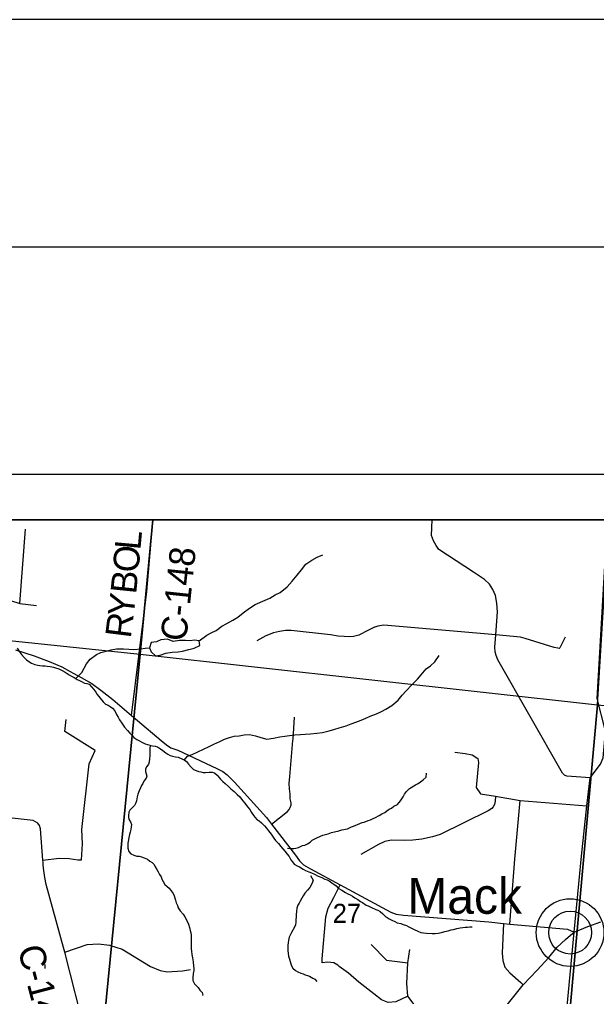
# Model space of a CAD drawing. Extents: x 0 to 34, y 0 to 22.
# Drawn here: x 4.78 to 6.05, y 19.852 to 22 of the extents above; entities that cross this region are included whole.
import ezdxf

# ---------------------------------------------------------------- set-up
doc = ezdxf.new("R2010")
doc.units = 0
for name, color, linetype in [('GM_X_Corporation', 7, 'Continuous'), ('GM_X_County_Road', 7, 'Continuous'), ('GM_X_County_Road_Text', 7, 'Continuous'), ('GM_X_Minor_Lake', 7, 'Continuous'), ('GM_X_Minor_River', 7, 'Continuous'), ('GM_X_Section_Text', 7, 'Continuous'), ('GM_X_State_Route', 7, 'Continuous'), ('GM_X_Township_Road', 7, 'Continuous'), ('GM_X_Unincorporated', 7, 'Continuous'), ('GM_X_Unincorporated_Location', 7, 'Continuous'), ('GM_X_Unincorporated_Text', 7, 'Continuous'), ('SH_Border', 7, 'Continuous'), ('SH_Cut_Line', 7, 'Continuous'), ('SH_Data', 7, 'Continuous')]:
    doc.layers.add(name, color=color, linetype=linetype)

msp = doc.modelspace()

# ---------------------------------------------------------------- linework, layer by layer
at = {"layer": 'GM_X_Corporation'}
for points in [[(8.9, 14.3814), (8.9, 20.9), (2.1, 20.9)], [(8.9, 17.1766), (8.9, 20.9), (4.0645, 20.9), (4.0111, 20.3696), (4.0006, 20.2658), (3.9936, 20.1954), (3.918, 19.4442), (3.8667, 18.9339), (3.8234, 18.553), (3.8126, 18.3974), (3.8023, 18.3182), (3.7454, 17.7286)]]:
    msp.add_lwpolyline(points, dxfattribs=at)
for points in [[(5.0731, 20.9), (4.0674, 20.9), (4.0476, 20.7082), (5.0456, 20.6041)], [(6.077, 20.9), (5.0731, 20.9), (5.0456, 20.6041), (6.0521, 20.4929)], [(4.0476, 20.7082), (5.0456, 20.6041), (4.9462, 19.5973), (3.9403, 19.7031)], [(6.0521, 20.4929), (5.9616, 19.4927), (4.9462, 19.5973), (5.0456, 20.6041)], [(7.0465, 20.3953), (6.9413, 19.3834), (5.9616, 19.4927), (6.0521, 20.4929)]]:
    msp.add_lwpolyline(points, close=True, dxfattribs=at)
at = {"layer": 'GM_X_County_Road'}
for points in [[(5.0263, 20.4698), (5.0598, 20.7421), (5.0709, 20.8695), (5.0742, 20.9)], [(6.0357, 20.3327), (5.9847, 20.3361), (5.9794, 20.3382), (5.975, 20.3429), (5.8326, 20.5921), (5.8291, 20.6013), (5.8268, 20.6093), (5.8263, 20.6196), (5.8283, 20.6466), (5.8319, 20.6973), (5.8303, 20.7167), (5.8274, 20.7335), (5.8218, 20.747), (5.8142, 20.7586), (5.8035, 20.7684), (5.779, 20.7844), (5.7029, 20.8343), (5.6968, 20.8433), (5.6908, 20.8538), (5.6869, 20.8656), (5.6878, 20.9)], [(6.0357, 20.3327), (6.0589, 20.3625), (6.0642, 20.3768), (6.0699, 20.4348), (6.0514, 20.507), (6.0739, 20.9)], [(4.7713, 20.6137), (4.8119, 20.6005), (4.8454, 20.5882), (4.8732, 20.5765), (4.8915, 20.5665), (4.9154, 20.5533), (4.939, 20.5402), (4.9587, 20.5256), (4.9851, 20.5048), (5.0263, 20.4698)], [(5.0263, 20.4698), (5.0396, 20.4585), (5.092, 20.4146), (5.1031, 20.4048), (5.1132, 20.3988), (5.1282, 20.3935), (5.2144, 20.3532), (5.2275, 20.3464), (5.2368, 20.3393), (5.2531, 20.323), (5.3235, 20.2455), (5.3348, 20.2308), (5.3873, 20.1625), (5.3964, 20.1497), (5.4053, 20.1411), (5.4206, 20.1324), (5.4859, 20.0972)], [(6.0003, 19.9928), (6.0164, 20.1604), (6.0288, 20.2712), (6.0357, 20.3327)], [(4.8321, 20.1419), (4.8317, 20.1469), (4.8314, 20.1513), (4.8263, 20.2202), (4.8238, 20.2275), (4.8202, 20.2325), (4.8097, 20.2385), (4.6962, 20.251)], [(4.9258, 19.7674), (4.8794, 19.9495), (4.8769, 19.9594), (4.8389, 20.0979), (4.8359, 20.1136), (4.8327, 20.1338), (4.8321, 20.1419)], [(5.4859, 20.0972), (5.5972, 20.0373), (5.6092, 20.0324), (5.6251, 20.0305), (5.813, 20.0156), (5.8451, 20.0124)], [(5.8451, 20.0124), (5.8423, 19.9472), (5.8438, 19.9306), (5.8477, 19.916), (5.8588, 19.9036), (5.8836, 19.8823), (5.8884, 19.8772)], [(5.8451, 20.0124), (5.859, 20.011), (5.9861, 19.9994), (6.0003, 19.9928)], [(5.9168, 18.9788), (5.9313, 19.1438), (5.9319, 19.1508), (5.942, 19.291), (5.9466, 19.3546), (5.9513, 19.4191), (5.9555, 19.4438), (5.9566, 19.4892), (5.9673, 19.6321), (5.979, 19.7684), (6.0003, 19.9928)]]:
    msp.add_lwpolyline(points, dxfattribs=at)
at = {"layer": 'GM_X_Minor_Lake'}
for points in [[(5.1179, 20.6324), (5.1055, 20.6373), (5.091, 20.6358), (5.0811, 20.6319), (5.07, 20.6299), (5.0663, 20.6185)], [(5.0663, 20.6186), (5.0694, 20.6094), (5.0795, 20.6011), (5.0894, 20.602), (5.1021, 20.607), (5.1158, 20.6085), (5.1291, 20.6093), (5.1386, 20.611), (5.1528, 20.6144), (5.1643, 20.6175), (5.177, 20.6233), (5.175, 20.634), (5.1651, 20.6354), (5.1552, 20.6337), (5.1453, 20.6344), (5.1317, 20.6343), (5.1179, 20.6324)]]:
    msp.add_lwpolyline(points, dxfattribs=at)
at = {"layer": 'GM_X_Minor_River'}
for points in [[(5.175, 20.634), (5.1919, 20.6465), (5.2015, 20.6512), (5.2127, 20.6566), (5.2255, 20.6657), (5.2359, 20.6719), (5.2494, 20.6795), (5.2602, 20.686), (5.2723, 20.6955), (5.2862, 20.7054), (5.2986, 20.7134), (5.3209, 20.7234), (5.3306, 20.7277), (5.3429, 20.735), (5.3533, 20.74), (5.3693, 20.7525), (5.3799, 20.7651), (5.3913, 20.7781), (5.4003, 20.79), (5.4098, 20.8026), (5.423, 20.8114), (5.4353, 20.8175), (5.4476, 20.8232)], [(4.7748, 20.6174), (4.7802, 20.6097), (4.7842, 20.6034), (4.79, 20.5968), (4.7956, 20.592), (4.8004, 20.5884), (4.8063, 20.5848), (4.8138, 20.5819), (4.8202, 20.5802), (4.8248, 20.5796), (4.8304, 20.5787), (4.8361, 20.5785), (4.841, 20.5779), (4.8471, 20.5773), (4.855, 20.5759), (4.8595, 20.5746), (4.8666, 20.5725), (4.8741, 20.5684), (4.8804, 20.5648), (4.8893, 20.5591), (4.8946, 20.5563), (4.9001, 20.5531), (4.9065, 20.549), (4.9121, 20.5466), (4.918, 20.5437), (4.9229, 20.5409), (4.9278, 20.5396), (4.933, 20.5382), (4.9385, 20.5324), (4.9437, 20.5265), (4.948, 20.5206), (4.9505, 20.5156), (4.9571, 20.5078), (4.9644, 20.4995), (4.9691, 20.4948), (4.9747, 20.492), (4.9792, 20.4895)], [(4.9039, 20.5507), (4.9172, 20.5639), (4.9224, 20.5736), (4.9272, 20.5834), (4.9351, 20.5938), (4.9491, 20.604), (4.9587, 20.6079), (4.9706, 20.6114), (4.9813, 20.6138), (4.9935, 20.6161), (5.0091, 20.616), (5.0204, 20.6153), (5.0318, 20.615), (5.0467, 20.6165), (5.0562, 20.6177), (5.0663, 20.6186)], [(5.143, 20.3718), (5.1496, 20.3801), (5.16, 20.384), (5.1723, 20.3894), (5.1846, 20.3955), (5.1977, 20.4016), (5.2073, 20.4062), (5.2208, 20.4123), (5.2312, 20.4177), (5.2423, 20.4212), (5.2523, 20.4239), (5.263, 20.4252), (5.2744, 20.4271), (5.2858, 20.4279), (5.299, 20.4249), (5.3107, 20.4211), (5.3243, 20.4173), (5.3388, 20.4196), (5.3525, 20.4226), (5.3636, 20.4242), (5.3743, 20.4258), (5.3861, 20.427), (5.3986, 20.4281), (5.4089, 20.4286), (5.4207, 20.4294), (5.434, 20.4309), (5.447, 20.4321), (5.4615, 20.4355), (5.4742, 20.4393), (5.4837, 20.4421), (5.4987, 20.447), (5.5095, 20.4512), (5.5198, 20.4551), (5.5321, 20.4593), (5.5421, 20.4636), (5.5517, 20.4679), (5.5655, 20.4732), (5.5763, 20.4782), (5.5864, 20.4836), (5.5991, 20.4912), (5.6131, 20.5034), (5.6222, 20.5141), (5.6308, 20.5238), (5.6433, 20.5371), (5.6559, 20.5493), (5.6641, 20.5593), (5.6747, 20.5719), (5.6844, 20.5785), (5.6942, 20.5877), (5.7037, 20.6015)], [(4.9792, 20.4895), (4.9844, 20.4856), (4.9895, 20.4797), (4.9934, 20.4719), (4.9974, 20.4657), (4.9998, 20.4599), (5.0049, 20.4525), (5.011, 20.4436), (5.0176, 20.4369), (5.0227, 20.431), (5.0275, 20.4263), (5.0319, 20.4212), (5.0382, 20.4168), (5.0442, 20.4136), (5.049, 20.4111), (5.0565, 20.4074), (5.0617, 20.4057), (5.0666, 20.4044), (5.0727, 20.4031), (5.0787, 20.4021), (5.0836, 20.4004), (5.0903, 20.3964), (5.0955, 20.3928), (5.1017, 20.3876), (5.1062, 20.3848), (5.1114, 20.3816), (5.1167, 20.3799), (5.1231, 20.3789), (5.1291, 20.3776), (5.137, 20.3746), (5.1426, 20.3722), (5.1478, 20.3686), (5.1518, 20.3627), (5.158, 20.3557), (5.1631, 20.3509), (5.1684, 20.3488), (5.174, 20.3467), (5.1793, 20.3454), (5.1838, 20.3445), (5.1891, 20.3439), (5.1975, 20.3452), (5.2043, 20.3453), (5.2088, 20.3436), (5.2151, 20.3381), (5.222, 20.3299), (5.2275, 20.3244), (5.2327, 20.3204), (5.24, 20.3137), (5.2452, 20.3086), (5.2522, 20.3026), (5.2592, 20.2959), (5.2651, 20.2904), (5.2709, 20.283), (5.2756, 20.2771), (5.2818, 20.2685), (5.2865, 20.2627), (5.2908, 20.2564), (5.2937, 20.2518), (5.2981, 20.2459), (5.3032, 20.24), (5.3077, 20.2376), (5.3128, 20.2332), (5.3191, 20.227), (5.3234, 20.2219), (5.3282, 20.216), (5.3336, 20.2086), (5.3398, 20.2), (5.3434, 20.1949), (5.3496, 20.1879), (5.3547, 20.1813), (5.3591, 20.1765), (5.3635, 20.1714), (5.3693, 20.1648), (5.3737, 20.1597), (5.3768, 20.1524), (5.3809, 20.1477), (5.3845, 20.143), (5.3908, 20.1393), (5.3964, 20.1365), (5.4042, 20.132), (5.4094, 20.1284), (5.4166, 20.1259), (5.4222, 20.1234), (5.4289, 20.1209), (5.4375, 20.1164), (5.4454, 20.1135), (5.4521, 20.1098), (5.4569, 20.1082), (5.4614, 20.1061), (5.4673, 20.1013), (5.4718, 20.0985), (5.4766, 20.0949), (5.4814, 20.0902), (5.4896, 20.0854), (5.4974, 20.0802), (5.5026, 20.0773), (5.5078, 20.0749), (5.5127, 20.0724), (5.5182, 20.0688), (5.5242, 20.0652), (5.5301, 20.0608)], [(5.0676, 20.4042), (5.0667, 20.3964), (5.0669, 20.3903), (5.0666, 20.3812), (5.066, 20.3748), (5.065, 20.3672), (5.0637, 20.3627), (5.0601, 20.3575), (5.0569, 20.3523), (5.0574, 20.3462), (5.0588, 20.3412), (5.0605, 20.3362), (5.0584, 20.3314), (5.0533, 20.3251), (5.0512, 20.3198), (5.0487, 20.3153), (5.0459, 20.3105), (5.043, 20.3038), (5.0405, 20.2966), (5.0392, 20.291), (5.0383, 20.2864), (5.0377, 20.2819), (5.0357, 20.2774), (5.0328, 20.2714), (5.0281, 20.2663), (5.023, 20.2611), (5.0205, 20.2567), (5.0195, 20.2498), (5.0198, 20.2453), (5.0211, 20.2403), (5.024, 20.2356), (5.0261, 20.2302), (5.0259, 20.2245), (5.0249, 20.2189), (5.0236, 20.2128), (5.0223, 20.2079), (5.0205, 20.2012), (5.0196, 20.1963), (5.0182, 20.1887), (5.018, 20.1826), (5.0182, 20.1777), (5.0206, 20.1704), (5.025, 20.1657), (5.0313, 20.1628), (5.0385, 20.1606), (5.043, 20.1605), (5.0487, 20.1588), (5.0546, 20.1563), (5.0614, 20.1538), (5.0669, 20.149), (5.0718, 20.1462), (5.0765, 20.1418), (5.0787, 20.1368), (5.0819, 20.1306), (5.0851, 20.126), (5.0883, 20.1198), (5.0916, 20.1147), (5.0933, 20.1093), (5.0958, 20.1043), (5.0997, 20.0977), (5.1049, 20.0934), (5.1093, 20.0902), (5.1137, 20.0843), (5.118, 20.0781), (5.1201, 20.0727), (5.1236, 20.0634), (5.1249, 20.0577), (5.1273, 20.0515), (5.1294, 20.0465), (5.1338, 20.0403), (5.14, 20.0328), (5.1436, 20.0266), (5.1479, 20.0189), (5.1521, 20.0108), (5.1541, 20.0031), (5.1558, 19.997), (5.1568, 19.992), (5.1574, 19.9866), (5.1575, 19.9806), (5.1577, 19.9752), (5.1579, 19.968), (5.1576, 19.9615), (5.1578, 19.9562), (5.1584, 19.9513), (5.1589, 19.944), (5.1606, 19.9364), (5.1618, 19.9276), (5.163, 19.918), (5.1636, 19.9131), (5.1634, 19.9085), (5.1624, 19.9021), (5.1614, 19.893), (5.1615, 19.8869), (5.1651, 19.8796), (5.1728, 19.8713), (5.1771, 19.8659), (5.1819, 19.8604), (5.1836, 19.8546), (5.1838, 19.8538)], [(5.3697, 20.1777), (5.3785, 20.177), (5.3834, 20.1772), (5.3884, 20.1778), (5.3937, 20.1795), (5.403, 20.1834), (5.4076, 20.1847), (5.4134, 20.1872), (5.4196, 20.1908), (5.4243, 20.1956), (5.4343, 20.2005), (5.4424, 20.2041), (5.4478, 20.2062), (5.4536, 20.2082), (5.4589, 20.2092), (5.4662, 20.2124), (5.4731, 20.2136), (5.4827, 20.2156), (5.4896, 20.218), (5.5015, 20.2206), (5.5107, 20.2245), (5.5153, 20.2259), (5.5292, 20.2322), (5.5338, 20.234), (5.5384, 20.2353), (5.5473, 20.2384), (5.5526, 20.2405), (5.5584, 20.243), (5.5634, 20.2455), (5.5716, 20.2498), (5.577, 20.253), (5.5836, 20.2566), (5.5882, 20.2602), (5.5937, 20.2634), (5.5987, 20.2659), (5.6041, 20.2699), (5.6115, 20.2742), (5.6186, 20.2816), (5.6246, 20.2905), (5.6271, 20.2965), (5.6319, 20.3028), (5.6385, 20.309), (5.6513, 20.3169), (5.6571, 20.3202), (5.6626, 20.3238), (5.6684, 20.3281), (5.6747, 20.334), (5.6754, 20.3431)], [(5.4201, 20.1174), (5.4233, 20.1127), (5.4262, 20.1073), (5.4249, 20.1028), (5.4224, 20.0983), (5.4188, 20.0912), (5.4137, 20.0857), (5.4081, 20.0791), (5.4045, 20.0727), (5.4013, 20.0679), (5.3973, 20.0616), (5.3952, 20.0571), (5.3924, 20.0526), (5.3903, 20.0462), (5.3896, 20.0387), (5.389, 20.0322), (5.3884, 20.0151), (5.3871, 20.0091), (5.385, 20.0038), (5.3789, 19.9927), (5.3761, 19.9882), (5.3732, 19.9822), (5.3719, 19.975), (5.3709, 19.9705), (5.3703, 19.9637), (5.3701, 19.9565), (5.3703, 19.9519), (5.3709, 19.9469), (5.3722, 19.9404), (5.3742, 19.9339), (5.3759, 19.9285), (5.3769, 19.9236), (5.3787, 19.9189), (5.3815, 19.9139), (5.3871, 19.9091), (5.3923, 19.9059), (5.399, 19.903), (5.4039, 19.9013), (5.4087, 19.8993), (5.4136, 19.898), (5.4185, 19.8963), (5.4252, 19.8919), (5.4297, 19.8898), (5.4344, 19.8843)], [(5.5301, 20.0608), (5.5346, 20.058), (5.5427, 20.0527), (5.5472, 20.0507), (5.5547, 20.0474), (5.5641, 20.0433), (5.5685, 20.0416), (5.5738, 20.0387), (5.5793, 20.0336), (5.5844, 20.0285), (5.5889, 20.0253), (5.5937, 20.0221), (5.5993, 20.0192), (5.606, 20.0167), (5.6109, 20.0139), (5.6188, 20.0121), (5.624, 20.01), (5.6315, 20.0079), (5.6368, 20.005), (5.6442, 20.0013), (5.6487, 19.9993), (5.6569, 19.9956), (5.6629, 19.9927), (5.6693, 19.9913), (5.6758, 19.9907), (5.6879, 19.9903), (5.6944, 19.9905), (5.7012, 19.991), (5.7085, 19.9923), (5.7157, 19.9943), (5.7234, 19.9963), (5.7299, 19.998), (5.7349, 19.9993), (5.7422, 20.001), (5.7498, 20.0026), (5.7559, 20.0036), (5.7609, 20.0041), (5.7658, 20.0044), (5.7708, 20.0049), (5.7761, 20.0051)], [(4.8363, 19.9134), (4.8362, 19.9221)]]:
    msp.add_lwpolyline(points, dxfattribs=at)
at = {"layer": 'GM_X_State_Route'}
for points in [[(5.9928, 19.9866), (6.0003, 19.9928), (6.0309, 20.0057), (6.0594, 20.0158)], [(5.9191, 19.9097), (5.9451, 19.9373), (5.9633, 19.96), (5.9817, 19.9773), (5.9928, 19.9866)], [(5.2595, 19.6516), (5.2635, 19.6511), (5.323, 19.6493), (5.3504, 19.6498), (5.4101, 19.652), (5.4843, 19.6566), (5.5575, 19.6731), (5.6113, 19.6898), (5.6351, 19.6956), (5.6817, 19.707), (5.7032, 19.7123), (5.7513, 19.7272), (5.7644, 19.7337), (5.7938, 19.7596), (5.8011, 19.7684), (5.8884, 19.8772), (5.9191, 19.9097)]]:
    msp.add_lwpolyline(points, dxfattribs=at)
at = {"layer": 'GM_X_Township_Road'}
msp.add_line((4.7809, 20.7159), (4.7929, 20.879), dxfattribs=at)
for points in [[(4.7418, 20.728), (4.7809, 20.7159), (4.8172, 20.7115)], [(5.9806, 20.6416), (5.9692, 20.6181), (5.9685, 20.6175), (5.9675, 20.6172), (5.9646, 20.6174), (5.9567, 20.6188), (5.8929, 20.6387), (5.8828, 20.6417), (5.8283, 20.6466), (5.5816, 20.6679), (5.5687, 20.6663), (5.5618, 20.664), (5.5609, 20.6635)], [(5.5609, 20.6635), (5.5463, 20.6567), (5.527, 20.6461), (5.5148, 20.6432), (5.5054, 20.6424), (5.4945, 20.6435), (5.4813, 20.6442), (5.4645, 20.6466), (5.3778, 20.6567), (5.3653, 20.6563), (5.3519, 20.6546), (5.339, 20.6514), (5.3224, 20.6449), (5.302, 20.634)], [(4.8314, 20.1513), (4.8671, 20.1557), (4.8889, 20.1551), (4.9085, 20.1522), (4.9163, 20.1519), (4.9187, 20.1873), (4.9173, 20.2186), (4.933, 20.3632), (4.9467, 20.3926), (4.8798, 20.4342), (4.8828, 20.4611)], [(5.3818, 20.4145), (5.3821, 20.4176), (5.3849, 20.4659)], [(5.3348, 20.2308), (5.3694, 20.2583), (5.3734, 20.2629), (5.3758, 20.2675), (5.3777, 20.273), (5.3777, 20.2777), (5.3757, 20.2865), (5.3757, 20.2968), (5.3738, 20.3086), (5.3737, 20.3198), (5.3746, 20.3352), (5.3818, 20.4145)], [(5.7382, 20.3888), (5.7609, 20.3858), (5.776, 20.3828), (5.7887, 20.3751), (5.7903, 20.3661), (5.7853, 20.3116), (5.7943, 20.2975), (5.8278, 20.2919)], [(5.8278, 20.2919), (5.8268, 20.2811), (5.8253, 20.274), (5.8226, 20.269), (5.8191, 20.2653), (5.811, 20.2602), (5.7058, 20.208), (5.6892, 20.2027), (5.6656, 20.1975), (5.6458, 20.1955), (5.6262, 20.1949), (5.5988, 20.1952), (5.584, 20.1923), (5.5699, 20.1857), (5.5313, 20.1642)], [(5.8278, 20.2919), (5.882, 20.2828), (6.0288, 20.2712)], [(5.859, 20.011), (5.8703, 20.1533), (5.882, 20.2828)], [(5.4802, 19.9202), (5.4714, 19.926), (5.4586, 19.9269), (5.4461, 19.9256), (5.4462, 19.9345), (5.4541, 20.0268), (5.4593, 20.0457), (5.4714, 20.0692), (5.4859, 20.0972)], [(4.8794, 19.9495), (4.9286, 19.9662), (4.9541, 19.9674), (4.9777, 19.9648), (5.006, 19.9556), (5.0683, 19.9175), (5.0895, 19.909), (5.1048, 19.9062), (5.1389, 19.9081), (5.1561, 19.911)], [(5.5539, 19.9657), (5.5875, 19.9318), (5.6346, 19.926)], [(5.6817, 19.707), (5.672, 19.7508), (5.6699, 19.7626), (5.6704, 19.772), (5.6717, 19.7838), (5.6722, 19.7954), (5.6706, 19.8093), (5.6653, 19.8189), (5.651, 19.8312), (5.6346, 19.8526), (5.6323, 19.8804), (5.6346, 19.926), (5.6387, 19.9552)], [(5.6346, 19.8526), (5.6081, 19.8399), (5.591, 19.8388), (5.5767, 19.8444), (5.5594, 19.8572), (5.5266, 19.8832), (5.5042, 19.9028), (5.4837, 19.9178), (5.4802, 19.9202)]]:
    msp.add_lwpolyline(points, dxfattribs=at)
at = {"layer": 'GM_X_Unincorporated'}
for radius in [0.0744, 0.0472]:
    msp.add_circle((5.9917, 19.9923), radius, dxfattribs=at)
at = {"layer": 'GM_X_Unincorporated_Location'}
msp.add_line((5.9917, 19.9923), (5.9917, 19.9923), dxfattribs=at)
at = {"layer": 'SH_Border'}
msp.add_lwpolyline([(1.5, 21.5), (33.5, 21.5), (33.5, 0.5), (1.5, 0.5)], close=True, dxfattribs=at)
at = {"layer": 'SH_Cut_Line'}
msp.add_lwpolyline([(0, 0), (34, 0), (34, 22), (0, 22)], close=True, dxfattribs=at)
at = {"layer": 'SH_Data'}
for p, q in [((2, 21), (9, 21)), ((2.1, 20.9), (8.9, 20.9))]:
    msp.add_line(p, q, dxfattribs=at)

# ---------------------------------------------------------------- texts
at = {"layer": 'GM_X_County_Road_Text'}
for s, height, rotation, p in [('L', 0.0568, 84.8271, (5.0459, 20.8322)), ('O', 0.0568, 84.797, (5.0414, 20.7824)), ('C-148', 0.05682, 83.9636, (5.1466, 20.6313)), ('B', 0.0568, 84.1512, (5.0365, 20.7353)), ('Y', 0.0568, 83.1719, (5.0305, 20.6846)), ('R', 0.0568, 82.8755, (5.0247, 20.638)), ('C-144', 0.05682, 284.8258, (4.7755, 19.957))]:
    msp.add_text(s, height=height, rotation=rotation, dxfattribs=at).set_placement(p)
at = {"layer": 'GM_X_Section_Text'}
msp.add_text('27', height=0.04186, rotation=0, dxfattribs=at).set_placement((5.4693, 20.0136))
at = {"layer": 'GM_X_Unincorporated_Text'}
msp.add_text('Mack', height=0.07898, rotation=0, dxfattribs=at).set_placement((5.6335, 20.0335))

doc.saveas('drawing.dxf')
